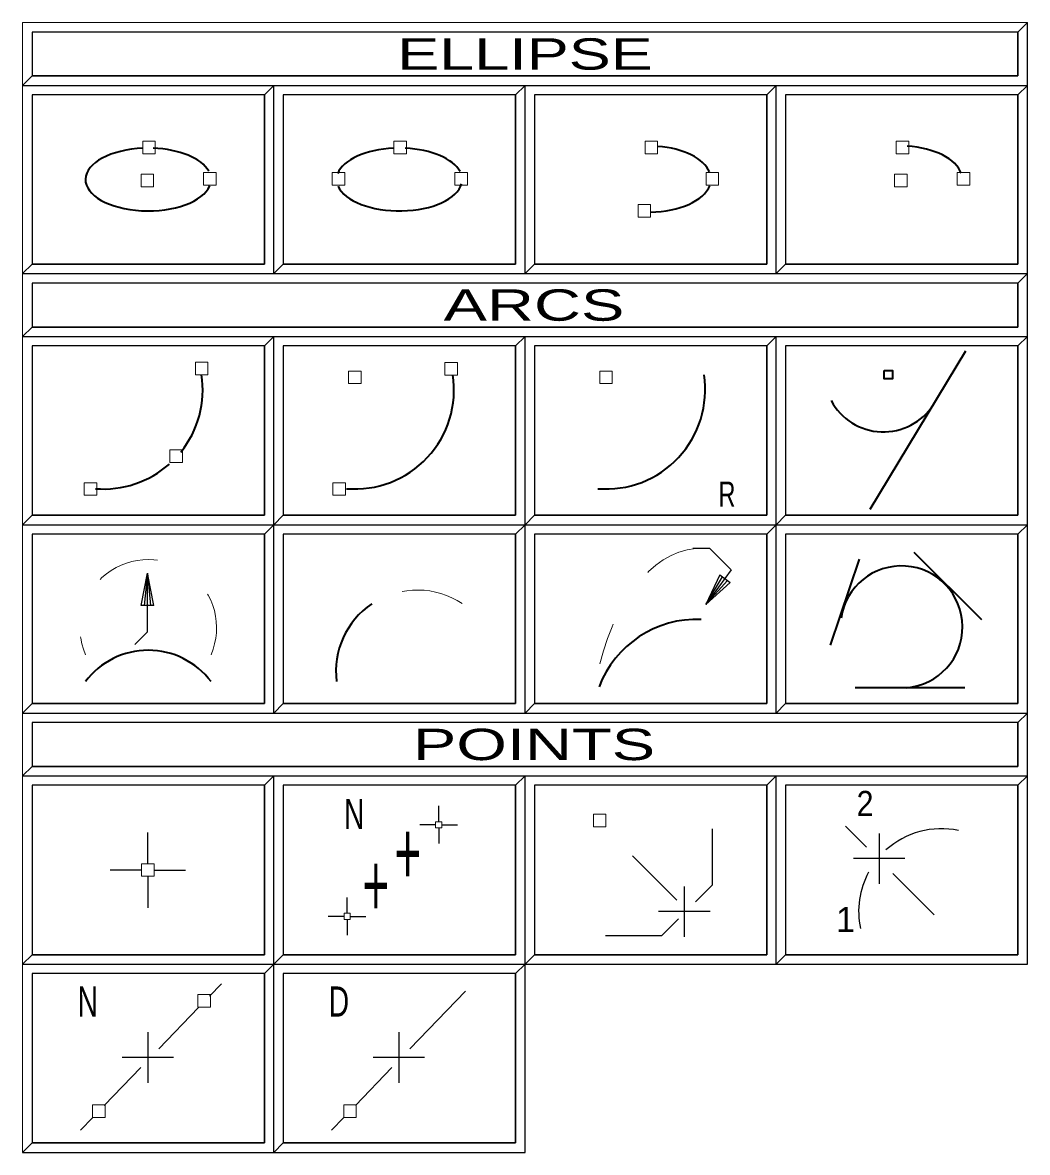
# Model space of a CAD drawing. Extents: x 95906.8 to 95923.6, y 90964.8 to 90972.8.
# Drawn here: x 95910.832 to 95912.432, y 90965.962 to 90967.762 of the extents above; entities that cross this region are included whole.
import ezdxf
from ezdxf.enums import TextEntityAlignment as Align

# ---------------------------------------------------------------- set-up
doc = ezdxf.new("R2010")
doc.units = 0
doc.header["$LTSCALE"] = 0.019
doc.linetypes.add('MEDIUM_DASHED', pattern=[4.5, 3, -1.5])
for name, color, linetype, lineweight in [('11', 7, 'Continuous', 25), ('12', 7, 'Continuous', 25), ('17', 7, 'Continuous', 25), ('2', 7, 'Continuous', 13), ('3', 7, 'Continuous', 25), ('6', 7, 'Continuous', 25), ('7', 7, 'Continuous', 35)]:
    doc.layers.add(name, color=color, linetype=linetype, lineweight=lineweight)

msp = doc.modelspace()

# ---------------------------------------------------------------- linework, layer by layer
at = {"layer": '11'}
for points in [[(95911.2473, 90967.3767), (95911.6173, 90967.3767), (95911.6173, 90967.6467), (95911.2473, 90967.6467)], [(95911.6473, 90967.3767), (95912.0173, 90967.3767), (95912.0173, 90967.6467), (95911.6473, 90967.6467)], [(95912.0473, 90967.3767), (95912.4173, 90967.3767), (95912.4173, 90967.6467), (95912.0473, 90967.6467)], [(95911.2473, 90966.9767), (95911.6173, 90966.9767), (95911.6173, 90967.2467), (95911.2473, 90967.2467)], [(95911.6473, 90966.9767), (95912.0173, 90966.9767), (95912.0173, 90967.2467), (95911.6473, 90967.2467)], [(95912.0473, 90966.9767), (95912.4173, 90966.9767), (95912.4173, 90967.2467), (95912.0473, 90967.2467)], [(95910.8473, 90966.6767), (95911.2173, 90966.6767), (95911.2173, 90966.9467), (95910.8473, 90966.9467)], [(95911.2473, 90966.6767), (95911.6173, 90966.6767), (95911.6173, 90966.9467), (95911.2473, 90966.9467)], [(95911.6473, 90966.6767), (95912.0173, 90966.6767), (95912.0173, 90966.9467), (95911.6473, 90966.9467)], [(95912.0473, 90966.6767), (95912.4173, 90966.6767), (95912.4173, 90966.9467), (95912.0473, 90966.9467)], [(95911.2473, 90966.2767), (95911.6173, 90966.2767), (95911.6173, 90966.5467), (95911.2473, 90966.5467)], [(95911.6473, 90966.2767), (95912.0173, 90966.2767), (95912.0173, 90966.5467), (95911.6473, 90966.5467)], [(95912.0473, 90966.2767), (95912.4173, 90966.2767), (95912.4173, 90966.5467), (95912.0473, 90966.5467)], [(95910.8473, 90965.9767), (95911.2173, 90965.9767), (95911.2173, 90966.2467), (95910.8473, 90966.2467)], [(95911.2473, 90965.9767), (95911.6173, 90965.9767), (95911.6173, 90966.2467), (95911.2473, 90966.2467)]]:
    msp.add_lwpolyline(points, close=True, dxfattribs=at)
at = {"layer": '12'}
for points in [[(95910.8473, 90967.3767), (95911.2173, 90967.3767), (95911.2173, 90967.6467), (95910.8473, 90967.6467)], [(95910.8473, 90966.9767), (95911.2173, 90966.9767), (95911.2173, 90967.2467), (95910.8473, 90967.2467)], [(95910.8473, 90966.2767), (95911.2173, 90966.2767), (95911.2173, 90966.5467), (95910.8473, 90966.5467)]]:
    msp.add_lwpolyline(points, close=True, dxfattribs=at)
at = {"layer": '17'}
for points in [[(95910.8473, 90967.6767), (95912.4173, 90967.6767), (95912.4173, 90967.7467), (95910.8473, 90967.7467)], [(95910.8473, 90967.2767), (95912.4173, 90967.2767), (95912.4173, 90967.3467), (95910.8473, 90967.3467)], [(95910.8473, 90966.5767), (95912.4173, 90966.5767), (95912.4173, 90966.6467), (95910.8473, 90966.6467)]]:
    msp.add_lwpolyline(points, close=True, dxfattribs=at)
at = {"layer": '2'}
for points in [[(95910.8323, 90967.7617), (95910.8323, 90967.6617), (95910.8473, 90967.6767), (95910.8473, 90967.7467), (95912.4173, 90967.7467), (95912.4323, 90967.7617)], [(95910.8323, 90967.6617), (95910.8323, 90967.3617), (95910.8473, 90967.3767), (95910.8473, 90967.6467), (95911.2173, 90967.6467), (95911.2323, 90967.6617)], [(95911.2323, 90967.6617), (95911.2323, 90967.3617), (95911.2473, 90967.3767), (95911.2473, 90967.6467), (95911.6173, 90967.6467), (95911.6323, 90967.6617)], [(95911.6323, 90967.6617), (95911.6323, 90967.3617), (95911.6473, 90967.3767), (95911.6473, 90967.6467), (95912.0173, 90967.6467), (95912.0323, 90967.6617)], [(95912.0323, 90967.6617), (95912.0323, 90967.3617), (95912.0473, 90967.3767), (95912.0473, 90967.6467), (95912.4173, 90967.6467), (95912.4323, 90967.6617)], [(95910.8323, 90967.3617), (95910.8323, 90967.2617), (95910.8473, 90967.2767), (95910.8473, 90967.3467), (95912.4173, 90967.3467), (95912.4323, 90967.3617)], [(95910.8323, 90967.2617), (95910.8323, 90966.9617), (95910.8473, 90966.9767), (95910.8473, 90967.2467), (95911.2173, 90967.2467), (95911.2323, 90967.2617)], [(95911.2323, 90967.2617), (95911.2323, 90966.9617), (95911.2473, 90966.9767), (95911.2473, 90967.2467), (95911.6173, 90967.2467), (95911.6323, 90967.2617)], [(95911.6323, 90967.2617), (95911.6323, 90966.9617), (95911.6473, 90966.9767), (95911.6473, 90967.2467), (95912.0173, 90967.2467), (95912.0323, 90967.2617)], [(95912.0323, 90967.2617), (95912.0323, 90966.9617), (95912.0473, 90966.9767), (95912.0473, 90967.2467), (95912.4173, 90967.2467), (95912.4323, 90967.2617)], [(95910.8323, 90966.9617), (95910.8323, 90966.6617), (95910.8473, 90966.6767), (95910.8473, 90966.9467), (95911.2173, 90966.9467), (95911.2323, 90966.9617)], [(95911.2323, 90966.9617), (95911.2323, 90966.6617), (95911.2473, 90966.6767), (95911.2473, 90966.9467), (95911.6173, 90966.9467), (95911.6323, 90966.9617)], [(95911.6323, 90966.9617), (95911.6323, 90966.6617), (95911.6473, 90966.6767), (95911.6473, 90966.9467), (95912.0173, 90966.9467), (95912.0323, 90966.9617)], [(95912.0323, 90966.9617), (95912.0323, 90966.6617), (95912.0473, 90966.6767), (95912.0473, 90966.9467), (95912.4173, 90966.9467), (95912.4323, 90966.9617)], [(95910.8323, 90966.6617), (95910.8323, 90966.5617), (95910.8473, 90966.5767), (95910.8473, 90966.6467), (95912.4173, 90966.6467), (95912.4323, 90966.6617)], [(95910.8323, 90966.5617), (95910.8323, 90966.2617), (95910.8473, 90966.2767), (95910.8473, 90966.5467), (95911.2173, 90966.5467), (95911.2323, 90966.5617)], [(95911.2323, 90966.5617), (95911.2323, 90966.2617), (95911.2473, 90966.2767), (95911.2473, 90966.5467), (95911.6173, 90966.5467), (95911.6323, 90966.5617)], [(95911.6323, 90966.5617), (95911.6323, 90966.2617), (95911.6473, 90966.2767), (95911.6473, 90966.5467), (95912.0173, 90966.5467), (95912.0323, 90966.5617)], [(95912.0323, 90966.5617), (95912.0323, 90966.2617), (95912.0473, 90966.2767), (95912.0473, 90966.5467), (95912.4173, 90966.5467), (95912.4323, 90966.5617)], [(95910.8323, 90966.2617), (95910.8323, 90965.9617), (95910.8473, 90965.9767), (95910.8473, 90966.2467), (95911.2173, 90966.2467), (95911.2323, 90966.2617)], [(95911.2323, 90966.2617), (95911.2323, 90965.9617), (95911.2473, 90965.9767), (95911.2473, 90966.2467), (95911.6173, 90966.2467), (95911.6323, 90966.2617)]]:
    msp.add_lwpolyline(points, close=True, dxfattribs=at)
at = {"layer": '3'}
for points in [[(95910.8323, 90967.6617), (95912.4323, 90967.6617), (95912.4323, 90967.7617), (95912.4173, 90967.7467), (95912.4173, 90967.6767), (95910.8473, 90967.6767)], [(95910.8323, 90967.3617), (95911.2323, 90967.3617), (95911.2323, 90967.6617), (95911.2173, 90967.6467), (95911.2173, 90967.3767), (95910.8473, 90967.3767)], [(95911.2323, 90967.3617), (95911.6323, 90967.3617), (95911.6323, 90967.6617), (95911.6173, 90967.6467), (95911.6173, 90967.3767), (95911.2473, 90967.3767)], [(95911.6323, 90967.3617), (95912.0323, 90967.3617), (95912.0323, 90967.6617), (95912.0173, 90967.6467), (95912.0173, 90967.3767), (95911.6473, 90967.3767)], [(95912.0323, 90967.3617), (95912.4323, 90967.3617), (95912.4323, 90967.6617), (95912.4173, 90967.6467), (95912.4173, 90967.3767), (95912.0473, 90967.3767)], [(95910.8323, 90967.2617), (95912.4323, 90967.2617), (95912.4323, 90967.3617), (95912.4173, 90967.3467), (95912.4173, 90967.2767), (95910.8473, 90967.2767)], [(95910.8323, 90966.9617), (95911.2323, 90966.9617), (95911.2323, 90967.2617), (95911.2173, 90967.2467), (95911.2173, 90966.9767), (95910.8473, 90966.9767)], [(95911.2323, 90966.9617), (95911.6323, 90966.9617), (95911.6323, 90967.2617), (95911.6173, 90967.2467), (95911.6173, 90966.9767), (95911.2473, 90966.9767)], [(95911.6323, 90966.9617), (95912.0323, 90966.9617), (95912.0323, 90967.2617), (95912.0173, 90967.2467), (95912.0173, 90966.9767), (95911.6473, 90966.9767)], [(95912.0323, 90966.9617), (95912.4323, 90966.9617), (95912.4323, 90967.2617), (95912.4173, 90967.2467), (95912.4173, 90966.9767), (95912.0473, 90966.9767)], [(95910.8323, 90966.6617), (95911.2323, 90966.6617), (95911.2323, 90966.9617), (95911.2173, 90966.9467), (95911.2173, 90966.6767), (95910.8473, 90966.6767)], [(95911.2323, 90966.6617), (95911.6323, 90966.6617), (95911.6323, 90966.9617), (95911.6173, 90966.9467), (95911.6173, 90966.6767), (95911.2473, 90966.6767)], [(95911.6323, 90966.6617), (95912.0323, 90966.6617), (95912.0323, 90966.9617), (95912.0173, 90966.9467), (95912.0173, 90966.6767), (95911.6473, 90966.6767)], [(95912.0323, 90966.6617), (95912.4323, 90966.6617), (95912.4323, 90966.9617), (95912.4173, 90966.9467), (95912.4173, 90966.6767), (95912.0473, 90966.6767)], [(95910.8323, 90966.5617), (95912.4323, 90966.5617), (95912.4323, 90966.6617), (95912.4173, 90966.6467), (95912.4173, 90966.5767), (95910.8473, 90966.5767)], [(95910.8323, 90966.2617), (95911.2323, 90966.2617), (95911.2323, 90966.5617), (95911.2173, 90966.5467), (95911.2173, 90966.2767), (95910.8473, 90966.2767)], [(95911.2323, 90966.2617), (95911.6323, 90966.2617), (95911.6323, 90966.5617), (95911.6173, 90966.5467), (95911.6173, 90966.2767), (95911.2473, 90966.2767)], [(95911.6323, 90966.2617), (95912.0323, 90966.2617), (95912.0323, 90966.5617), (95912.0173, 90966.5467), (95912.0173, 90966.2767), (95911.6473, 90966.2767)], [(95912.0323, 90966.2617), (95912.4323, 90966.2617), (95912.4323, 90966.5617), (95912.4173, 90966.5467), (95912.4173, 90966.2767), (95912.0473, 90966.2767)], [(95910.8323, 90965.9617), (95911.2323, 90965.9617), (95911.2323, 90966.2617), (95911.2173, 90966.2467), (95911.2173, 90965.9767), (95910.8473, 90965.9767)], [(95911.2323, 90965.9617), (95911.6323, 90965.9617), (95911.6323, 90966.2617), (95911.6173, 90966.2467), (95911.6173, 90965.9767), (95911.2473, 90965.9767)]]:
    msp.add_lwpolyline(points, close=True, dxfattribs=at)
at = {"layer": '6', "lineweight": 35}
for p, q in [((95912.182, 90966.9864), (95912.3345, 90967.2387)), ((95912.1187, 90966.7698), (95912.1651, 90966.9071)), ((95912.2515, 90966.9178), (95912.3594, 90966.8108)), ((95912.3327, 90966.702), (95912.1579, 90966.702))]:
    msp.add_line(p, q, dxfattribs=at)
at = {"layer": '6'}
for p, q in [((95911.0311, 90966.8331), (95911.0311, 90966.8843)), ((95911.0311, 90966.8843), (95911.0359, 90966.8331)), ((95911.9205, 90966.8344), (95911.9467, 90966.8787)), ((95911.9505, 90966.8759), (95911.9205, 90966.8344)), ((95911.4949, 90966.4886), (95911.4949, 90966.5136)), ((95911.4899, 90966.4836), (95911.4649, 90966.4836)), ((95911.4949, 90966.4786), (95911.4949, 90966.4536)), ((95911.4999, 90966.4836), (95911.5249, 90966.4836)), ((95912.1425, 90966.4817), (95912.1761, 90966.4481)), ((95911.0317, 90966.4216), (95911.0317, 90966.4716)), ((95912.1962, 90966.4699), (95912.1962, 90966.3896)), ((95912.1553, 90966.4305), (95912.2372, 90966.4305)), ((95911.0217, 90966.4116), (95910.9717, 90966.4116)), ((95911.0417, 90966.4116), (95911.0917, 90966.4116)), ((95912.2841, 90966.34), (95912.2181, 90966.4061)), ((95911.0317, 90966.4016), (95911.0317, 90966.3516)), ((95911.886, 90966.3853), (95911.886, 90966.305)), ((95911.3491, 90966.3428), (95911.3491, 90966.3678)), ((95911.3441, 90966.3378), (95911.3191, 90966.3378)), ((95911.3491, 90966.3328), (95911.3491, 90966.3078)), ((95911.3541, 90966.3378), (95911.3791, 90966.3378)), ((95911.8451, 90966.3459), (95911.927, 90966.3459)), ((95911.1489, 90966.2305), (95911.13, 90966.2108)), ((95911.449, 90966.1266), (95911.5375, 90966.2188)), ((95911.049, 90966.1266), (95911.1122, 90966.1924)), ((95911.0315, 90966.153), (95911.0315, 90966.0727)), ((95911.4315, 90966.153), (95911.4315, 90966.0727)), ((95910.9622, 90966.0363), (95911.0205, 90966.0969)), ((95910.9906, 90966.1136), (95911.0725, 90966.1136)), ((95911.3622, 90966.0363), (95911.4205, 90966.0969)), ((95911.3906, 90966.1136), (95911.4725, 90966.1136)), ((95910.9243, 90965.9969), (95910.9439, 90966.0173)), ((95911.3243, 90965.9969), (95911.3439, 90966.0173))]:
    msp.add_line(p, q, dxfattribs=at)
at = {"layer": '6', "linetype": 'MEDIUM_DASHED', "lineweight": 13}
msp.add_line((95911.8743, 90966.3635), (95911.7593, 90966.4783), dxfattribs=at)
at = {"layer": '6', "lineweight": 13}
for points in [[(95911.0235, 90967.5526), (95911.0435, 90967.5526), (95911.0435, 90967.5726), (95911.0235, 90967.5726)], [(95911.4235, 90967.5526), (95911.4435, 90967.5526), (95911.4435, 90967.5726), (95911.4235, 90967.5726)], [(95911.8235, 90967.5526), (95911.8435, 90967.5526), (95911.8435, 90967.5726), (95911.8235, 90967.5726)], [(95912.2235, 90967.5526), (95912.2435, 90967.5526), (95912.2435, 90967.5726), (95912.2235, 90967.5726)], [(95911.0209, 90967.5001), (95911.0409, 90967.5001), (95911.0409, 90967.5201), (95911.0209, 90967.5201)], [(95911.1206, 90967.5027), (95911.1406, 90967.5027), (95911.1406, 90967.5227), (95911.1206, 90967.5227)], [(95911.3253, 90967.5027), (95911.3453, 90967.5027), (95911.3453, 90967.5227), (95911.3253, 90967.5227)], [(95911.5206, 90967.5027), (95911.5406, 90967.5027), (95911.5406, 90967.5227), (95911.5206, 90967.5227)], [(95911.9206, 90967.5027), (95911.9406, 90967.5027), (95911.9406, 90967.5227), (95911.9206, 90967.5227)], [(95912.2209, 90967.5001), (95912.2409, 90967.5001), (95912.2409, 90967.5201), (95912.2209, 90967.5201)], [(95912.3206, 90967.5027), (95912.3406, 90967.5027), (95912.3406, 90967.5227), (95912.3206, 90967.5227)], [(95911.8124, 90967.4517), (95911.8324, 90967.4517), (95911.8324, 90967.4717), (95911.8124, 90967.4717)], [(95911.1074, 90967.2005), (95911.1274, 90967.2005), (95911.1274, 90967.2205), (95911.1074, 90967.2205)], [(95911.5049, 90967.2001), (95911.5249, 90967.2001), (95911.5249, 90967.2201), (95911.5049, 90967.2201)], [(95911.3513, 90967.1865), (95911.3713, 90967.1865), (95911.3713, 90967.2065), (95911.3513, 90967.2065)], [(95911.7513, 90967.1865), (95911.7713, 90967.1865), (95911.7713, 90967.2065), (95911.7513, 90967.2065)], [(95911.0667, 90967.061), (95911.0867, 90967.061), (95911.0867, 90967.081), (95911.0667, 90967.081)], [(95910.9303, 90967.0086), (95910.9503, 90967.0086), (95910.9503, 90967.0286), (95910.9303, 90967.0286)], [(95911.3265, 90967.0086), (95911.3465, 90967.0086), (95911.3465, 90967.0286), (95911.3265, 90967.0286)], [(95911.7412, 90966.4806), (95911.7612, 90966.4806), (95911.7612, 90966.5006), (95911.7412, 90966.5006)], [(95911.7412, 90966.4806), (95911.7612, 90966.4806), (95911.7612, 90966.5006), (95911.7412, 90966.5006)], [(95911.4899, 90966.4786), (95911.4999, 90966.4786), (95911.4999, 90966.4886), (95911.4899, 90966.4886)], [(95911.4899, 90966.4786), (95911.4999, 90966.4786), (95911.4999, 90966.4886), (95911.4899, 90966.4886)], [(95911.0217, 90966.4016), (95911.0417, 90966.4016), (95911.0417, 90966.4216), (95911.0217, 90966.4216)], [(95911.3441, 90966.3328), (95911.3541, 90966.3328), (95911.3541, 90966.3428), (95911.3441, 90966.3428)], [(95911.3441, 90966.3328), (95911.3541, 90966.3328), (95911.3541, 90966.3428), (95911.3441, 90966.3428)], [(95911.1115, 90966.1931), (95911.1315, 90966.1931), (95911.1315, 90966.2131), (95911.1115, 90966.2131)], [(95911.1115, 90966.1931), (95911.1315, 90966.1931), (95911.1315, 90966.2131), (95911.1115, 90966.2131)], [(95910.9437, 90966.0175), (95910.9637, 90966.0175), (95910.9637, 90966.0375), (95910.9437, 90966.0375)], [(95910.9437, 90966.0175), (95910.9637, 90966.0175), (95910.9637, 90966.0375), (95910.9437, 90966.0375)], [(95911.3437, 90966.0175), (95911.3637, 90966.0175), (95911.3637, 90966.0375), (95911.3437, 90966.0375)], [(95911.3437, 90966.0175), (95911.3637, 90966.0175), (95911.3637, 90966.0375), (95911.3437, 90966.0375)]]:
    msp.add_lwpolyline(points, close=True, dxfattribs=at)
at = {"layer": '6', "lineweight": 35}
msp.add_lwpolyline([(95912.2043, 90967.2075), (95912.2177, 90967.2075), (95912.2177, 90967.1942), (95912.2043, 90967.1942)], close=True, dxfattribs=at)
at = {"layer": '6'}
for points in [[(95911.8994, 90966.9245), (95911.9263, 90966.9245), (95911.9608, 90966.89), (95911.9205, 90966.8344)], [(95911.011, 90966.7711), (95911.0311, 90966.7912), (95911.0311, 90966.8843)], [(95911.0413, 90966.8331), (95911.0209, 90966.8331), (95911.0311, 90966.8843)], [(95911.0413, 90966.8331), (95911.0311, 90966.8843), (95911.0261, 90966.8331)], [(95911.9423, 90966.8819), (95911.9588, 90966.8698), (95911.9205, 90966.8344)], [(95911.9423, 90966.8819), (95911.9205, 90966.8344), (95911.9546, 90966.8729)], [(95911.904, 90966.3609), (95911.9311, 90966.3881), (95911.931, 90966.4772)], [(95911.8769, 90966.3338), (95911.8498, 90966.3067), (95911.7607, 90966.3067)]]:
    msp.add_lwpolyline(points, dxfattribs=at)
at = {"layer": '6', "lineweight": 35}
for centre, radius, start, end in [((95910.9613, 90967.1765), 0.1579, 321.1842, 8.7525), ((95911.3613, 90967.1765), 0.1579, 265.2424, 8.7525), ((95911.7613, 90967.1765), 0.1579, 265.2424, 8.7525), ((95912.203, 90967.2043), 0.0947, 208.2947, 327.2812), ((95910.9613, 90967.1765), 0.1579, 265.2424, 311.6125), ((95912.2318, 90966.7989), 0.0972, 274.8279, 171.8685), ((95911.4606, 90966.7283), 0.1294, 124.0311, 187.3672), ((95911.9065, 90966.6437), 0.1674, 87.8498, 159.0411), ((95911.0323, 90966.6367), 0.125, 36.8699, 143.1301)]:
    msp.add_arc(centre, radius, start, end, dxfattribs=at)
at = {"layer": '6', "linetype": 'MEDIUM_DASHED', "lineweight": 13}
for centre, radius, start, end in [((95911.0323, 90966.7975), 0.1088, 336.7954, 203.2046), ((95911.4607, 90966.7282), 0.1295, 56.5459, 121.945)]:
    msp.add_arc(centre, radius, start, end, dxfattribs=at)
at = {"layer": '6'}
for start, end in [(78.0876, 132.0346), (151.6888, 191.9492)]:
    msp.add_arc((95912.2953, 90966.3457), 0.1317, start, end, dxfattribs=at)
at = {"layer": '6', "lineweight": 35}
for centre, major_axis, ratio, start_param, end_param in [((95911.0323, 90967.5117), (0.1, 0), 0.5, 1.652145, 6.081781), ((95911.0323, 90967.5117), (0.1, 0), 0.5, 0.273628, 1.493467), ((95911.4323, 90967.5117), (0.1, 0), 0.5, 1.662997, 2.947365), ((95911.4323, 90967.5117), (0.1, 0), 0.5, 0.260759, 1.478137), ((95911.8291, 90967.5124), (-0.0993, 0), 0.53093, 3.360642, 4.563617), ((95912.229, 90967.5124), (-0.0993, 0), 0.53093, 3.321217, 4.591689), ((95911.4323, 90967.5117), (0.1, 0), 0.5, 3.359628, 6.146211), ((95911.8291, 90967.5124), (-0.0993, 0), 0.53093, 1.599791, 2.939476)]:
    msp.add_ellipse(centre, major_axis=major_axis, ratio=ratio, start_param=start_param, end_param=end_param, dxfattribs=at)
at = {"layer": '6', "linetype": 'MEDIUM_DASHED', "lineweight": 13}
msp.add_ellipse((95911.9065, 90966.6437), major_axis=(0.0105, 0.2807), ratio=0.595849, start_param=6.283185, end_param=7.525708, dxfattribs=at)

# ---------------------------------------------------------------- texts
at = {"layer": '6'}
for s, height, width, p in [('R', 0.04, 0.7, (95911.9539, 90966.9904)), ('2', 0.04, 0.9, (95912.1738, 90966.4977)), ('N', 0.048, 0.7, (95911.3604, 90966.4769)), ('+', 0.1, 0.55, (95911.4457, 90966.389)), ('+', 0.1, 0.55, (95911.3948, 90966.338)), ('N', 0.048, 0.7, (95910.936, 90966.1781)), ('D', 0.048, 0.7, (95911.336, 90966.1781))]:
    msp.add_text(s, height=height, dxfattribs=dict(at, width=width)).set_placement(p, align=Align.CENTER)
msp.add_text('1', height=0.04, dxfattribs=at).set_placement((95912.1428, 90966.3128), align=Align.CENTER)
at = {"layer": '7'}
for s, width, p in [('        ELLIPSE        ', 1.5, (95911.6323, 90967.6867)), ('          ARCS         ', 1.55, (95911.6322, 90967.2867)), ('         POINTS        ', 1.55, (95911.6323, 90966.5867))]:
    msp.add_text(s, height=0.04999, dxfattribs=dict(at, width=width)).set_placement(p, align=Align.CENTER)

doc.saveas('drawing.dxf')
